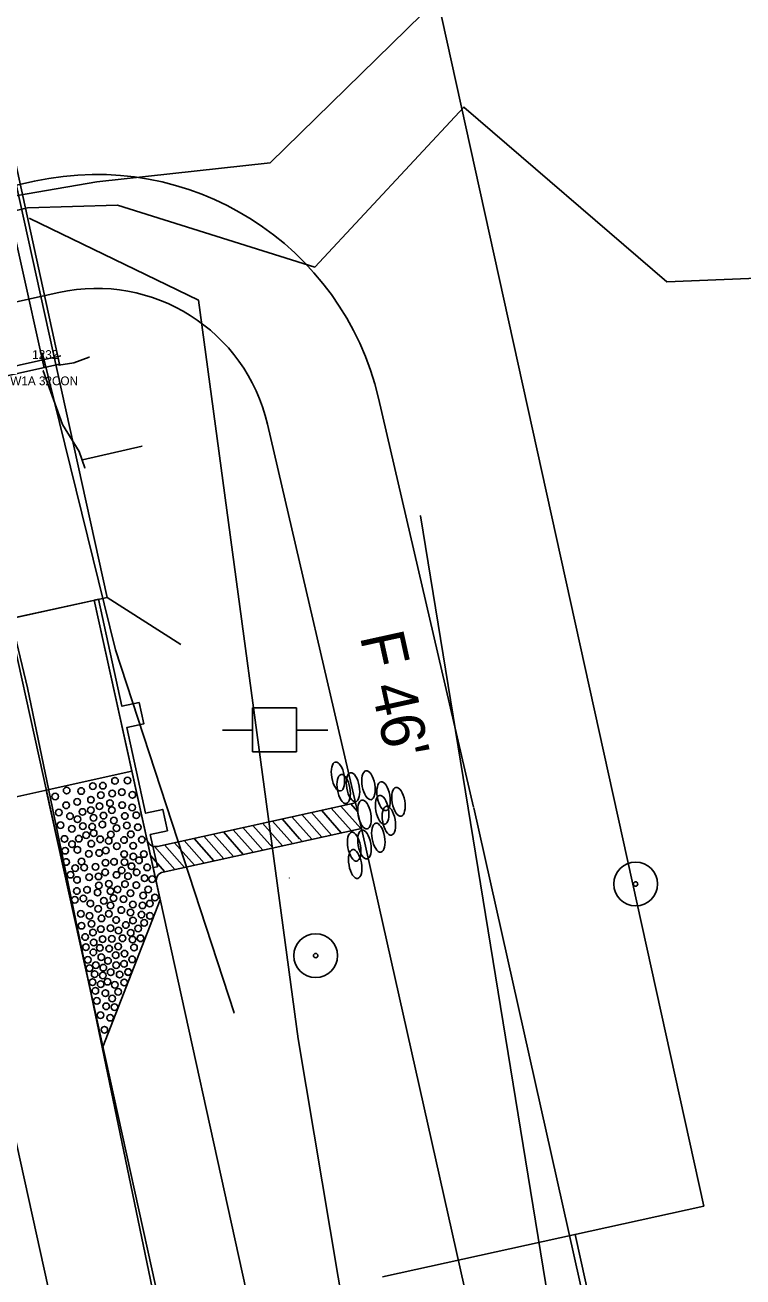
# Model space of a CAD drawing. Extents: x 2519952 to 2531965, y 848341 to 887632.
# Drawn here: x 2525647.4 to 2525729.3, y 850776.4 to 850919.3 of the extents above; entities that cross this region are included whole.
import ezdxf

# ---------------------------------------------------------------- set-up
doc = ezdxf.new("R2010")
doc.units = 0
for name, color, linetype in [('RD_EV_JW', 7, 'Continuous'), ('RD_EX_BldgApp', 7, 'Continuous'), ('RD_EX_BldgApp_txCode', 7, 'Continuous'), ('RD_EX_Bridge', 7, 'Continuous'), ('RD_EX_Conc', 7, 'Continuous'), ('RD_EX_DR_Pipe', 7, 'Continuous'), ('RD_EX_DV_Prop', 7, 'Continuous'), ('RD_EX_DV_PropPin', 7, 'Continuous'), ('RD_EX_GuardRail', 7, 'Continuous'), ('RD_EX_H2O', 7, 'Continuous'), ('RD_EX_Misc', 7, 'Continuous'), ('RD_EX_Road', 7, 'Continuous'), ('RD_EX_RW', 7, 'Continuous'), ('RD_EX_UT', 7, 'Continuous'), ('RD_EX_VEG', 7, 'Continuous'), ('RD_HC_Cl', 7, 'Continuous'), ('RD_PD_Bridge', 7, 'Continuous'), ('RD_PD_CstnLmt', 7, 'Continuous'), ('RD_PD_DR_ErosCtrl', 7, 'Continuous'), ('RD_PD_Final_TrvlWay', 7, 'Continuous'), ('RD_PD_GR', 7, 'Continuous'), ('RD_PD_PaveShd', 7, 'Continuous'), ('RD_PD_RW', 7, 'Continuous'), ('RD_PD_TX_CstnLmt', 7, 'Continuous'), ('RD_SMD_Locator', 7, 'Continuous')]:
    doc.layers.add(name, color=color, linetype=linetype)

# ---------------------------------------------------------------- blocks, each defined once
blk = doc.blocks.new('TBC1')
at = {"layer": 'RD_PD_GR'}
blk.add_lwpolyline([(12.5, 2.5), (15, 2.5), (15, 0.49), (25, 0.49), (25, 2.5), (27.5, 2.5), (27.5, 0.49), (31.25, 0.49), (31.25, 0), (0, 0), (0, 0.49), (12.5, 0.49)], close=True, dxfattribs=at)

msp = doc.modelspace()

# ---------------------------------------------------------------- linework, layer by layer
at = {"layer": 'RD_EV_JW'}
msp.add_lwpolyline([(2525775.02, 850342.8), (2525740.57, 850502.29), (2525718.16, 850607.75), (2525694.09, 850711.08), (2525678.58, 850803.56), (2525667.22, 850887.85), (2525647.98, 850897.19)], dxfattribs=at)
at = {"layer": 'RD_EX_BldgApp'}
msp.add_lwpolyline([(2525649.6, 850880.16), (2525641.48, 850916.68), (2525633.46, 850954.22)], dxfattribs=at)
at = {"layer": 'RD_EX_Bridge'}
for points in [[(2525605.06, 850870.31), (2525651.35, 850880.55), (2525635.22, 850954.61), (2525588.3, 850944.15), (2525605.06, 850870.31)], [(2525651.3, 850880.44), (2525653, 850880.72), (2525654.76, 850881.37)]]:
    msp.add_lwpolyline(points, dxfattribs=at)
at = {"layer": 'RD_EX_Conc'}
msp.add_lwpolyline([(2525654.27, 850868.73), (2525653.61, 850870.6), (2525651.69, 850873.67), (2525649.52, 850879.82)], dxfattribs=at)
at = {"layer": 'RD_EX_DR_Pipe'}
msp.add_line((2525654, 850869.64), (2525660.78, 850871.21), dxfattribs=at)
at = {"layer": 'RD_EX_DV_Prop'}
for p, q in [((2525660.31, 851077.44), (2525724.82, 850784.46)), ((2525724.82, 850784.46), (2525688.2, 850776.39))]:
    msp.add_line(p, q, dxfattribs=at)
at = {"layer": 'RD_EX_DV_PropPin'}
for centre, radius in [((2525717.05, 850821.24), 2.5), ((2525717.05, 850821.24), 0.25), ((2525680.57, 850813.07), 2.5), ((2525680.57, 850813.07), 0.25)]:
    msp.add_circle(centre, radius, dxfattribs=at)
at = {"layer": 'RD_EX_GuardRail'}
msp.add_lwpolyline([(2525671.27, 850806.53), (2525657.76, 850847.98), (2525649.43, 850881.8)], dxfattribs=at)
at = {"layer": 'RD_EX_H2O'}
for points in [[(2525412.97, 850559.06), (2525428.27, 850649.7), (2525457.74, 850694.47), (2525453.92, 850721), (2525416.74, 850748.14), (2525431.1, 850766.83), (2525463.21, 850790.4), (2525509.32, 850829.77), (2525574.87, 850869.61), (2525599.53, 850891.71), (2525655.63, 850901.38), (2525655.63, 850901.38), (2525675.39, 850903.55), (2525720.41, 850947.65)], [(2525657.98, 850898.71), (2525680.46, 850891.64), (2525697.48, 850909.91), (2525720.59, 850889.96), (2525757.95, 850891.5), (2525796.51, 850902.22), (2525808.33, 850876.08)], [(2525622.89, 850733.84), (2525593.83, 850844.27), (2525586.42, 850855.44), (2525600.63, 850887.26), (2525647.72, 850898.42), (2525657.98, 850898.71)]]:
    msp.add_lwpolyline(points, dxfattribs=at)
at = {"layer": 'RD_EX_Misc'}
msp.add_line((2525604.58, 850871.02), (2525651.5, 850881.5), dxfattribs=at)
at = {"layer": 'RD_EX_Road'}
for p, q in [((2525647.73, 850843.63), (2525639.53, 850877.6)), ((2525668.13, 850745.17), (2525647.73, 850843.63))]:
    msp.add_line(p, q, dxfattribs=at)
at = {"layer": 'RD_EX_RW'}
for p in [(2525660.31, 851077.44), (2525688.2, 850776.39)]:
    msp.add_line(p, (2525724.82, 850784.46), dxfattribs=at)
at = {"layer": 'RD_EX_UT'}
for p, q in [((2525678.38, 850841.34), (2525673.38, 850841.34)), ((2525673.38, 850841.34), (2525673.38, 850836.34)), ((2525678.38, 850836.34), (2525678.38, 850841.34)), ((2525669.95, 850838.78), (2525673.42, 850838.78)), ((2525678.31, 850838.78), (2525681.95, 850838.78)), ((2525673.38, 850836.34), (2525678.38, 850836.34))]:
    msp.add_line(p, q, dxfattribs=at)
at = {"layer": 'RD_EX_VEG'}
msp.add_lwpolyline([(2525828.9, 850368.68), (2525796.32, 850351.78), (2525755.08, 850564.16), (2525710.49, 850752.88), (2525692.51, 850863.27)], dxfattribs=at)
at = {"layer": 'RD_HC_Cl'}
msp.add_line((2525471.32, 851586.92), (2526027.91, 849059.27), dxfattribs=at)
at = {"layer": 'RD_PD_Bridge'}
for p, q in [((2525610.88, 850843.85), (2525656.79, 850853.95)), ((2525655.32, 850853.63), (2525659.62, 850834.1)), ((2525656.79, 850853.95), (2525665.21, 850848.57)), ((2525659.62, 850834.1), (2525616.65, 850824.64))]:
    msp.add_line(p, q, dxfattribs=at)
for points in [[(2525656.79, 850853.95), (2525628.83, 850980.91)], [(2525610.88, 850843.85), (2525656.79, 850853.95)]]:
    msp.add_lwpolyline(points, dxfattribs=at)
at = {"layer": 'RD_PD_CstnLmt'}
for p, q in [((2525675.07, 850873.73), (2525685.91, 850827.08)), ((2525685.91, 850827.08), (2525707.76, 850729.5))]:
    msp.add_line(p, q, dxfattribs=at)
msp.add_lwpolyline([(2525600.75, 850877.61), (2525651.29, 850888.74)], dxfattribs=at)
msp.add_arc((2525655.59, 850869.21), 20, 13.0724, 102.4185, dxfattribs=at)
at = {"layer": 'RD_PD_DR_ErosCtrl'}
for p, q in [((2525687.74, 850876.67), (2525698.57, 850830.02)), ((2525698.59, 850829.93), (2525720.45, 850732.34))]:
    msp.add_line(p, q, dxfattribs=at)
msp.add_lwpolyline([(2525597.95, 850890.31), (2525648.5, 850901.44)], dxfattribs=at)
msp.add_arc((2525655.59, 850869.21), 33, 13.0724, 102.4185, dxfattribs=at)
at = {"layer": 'RD_PD_Final_TrvlWay'}
msp.add_line((2525571.9, 851185.96), (2525846.09, 849940.79), dxfattribs=at)
at = {"layer": 'RD_PD_GR'}
msp.add_line((2525662.04, 850823.11), (2525820.64, 850102.87), dxfattribs=at)
at = {"layer": 'RD_PD_PaveShd'}
for p, q in [((2525649.86, 850831.95), (2525659.62, 850834.1)), ((2525659.62, 850834.1), (2525661.56, 850825.31)), ((2525649.86, 850831.95), (2525656.31, 850802.65)), ((2525685.11, 850830.51), (2525662.53, 850825.52)), ((2525683.45, 850830.14), (2525685.73, 850827.57)), ((2525683.45, 850830.14), (2525685.73, 850827.57)), ((2525684.57, 850830.39), (2525685.34, 850829.52)), ((2525685.79, 850827.59), (2525685.11, 850830.51)), ((2525676.75, 850828.66), (2525678.74, 850826.41)), ((2525676.75, 850828.66), (2525679.03, 850826.09)), ((2525677.87, 850828.91), (2525680.14, 850826.34)), ((2525677.87, 850828.91), (2525680.14, 850826.34)), ((2525678.99, 850829.16), (2525681.26, 850826.59)), ((2525678.99, 850829.16), (2525681.26, 850826.59)), ((2525680.1, 850829.4), (2525682.38, 850826.83)), ((2525680.1, 850829.4), (2525682.38, 850826.83)), ((2525681.22, 850829.65), (2525683.49, 850827.08)), ((2525681.22, 850829.65), (2525683.49, 850827.08)), ((2525682.34, 850829.9), (2525684.61, 850827.33)), ((2525682.34, 850829.9), (2525684.61, 850827.33)), ((2525663.18, 850822.59), (2525685.79, 850827.59)), ((2525670.05, 850827.18), (2525672.32, 850824.61)), ((2525670.05, 850827.18), (2525672.32, 850824.61)), ((2525671.17, 850827.43), (2525673.44, 850824.86)), ((2525671.17, 850827.43), (2525673.44, 850824.86)), ((2525672.28, 850827.68), (2525674.56, 850825.11)), ((2525672.28, 850827.68), (2525674.56, 850825.11)), ((2525673.4, 850827.92), (2525675.67, 850825.35)), ((2525673.4, 850827.92), (2525675.67, 850825.35)), ((2525674.52, 850828.17), (2525676.79, 850825.6)), ((2525674.52, 850828.17), (2525676.79, 850825.6)), ((2525675.63, 850828.42), (2525677.91, 850825.85)), ((2525675.63, 850828.42), (2525677.91, 850825.85)), ((2525663.35, 850825.7), (2525665.62, 850823.13)), ((2525663.35, 850825.7), (2525665.62, 850823.13)), ((2525664.46, 850825.95), (2525666.74, 850823.38)), ((2525664.46, 850825.95), (2525666.74, 850823.38)), ((2525665.58, 850826.2), (2525667.85, 850823.63)), ((2525665.58, 850826.2), (2525667.85, 850823.63)), ((2525666.7, 850826.44), (2525668.97, 850823.87)), ((2525667.82, 850826.69), (2525670.09, 850824.12)), ((2525667.82, 850826.69), (2525670.09, 850824.12)), ((2525668.93, 850826.94), (2525671.21, 850824.37)), ((2525668.93, 850826.94), (2525671.21, 850824.37)), ((2525661.56, 850825.31), (2525662.2, 850822.38)), ((2525661.73, 850824.51), (2525663.39, 850822.64)), ((2525662.18, 850825.51), (2525664.5, 850822.89)), ((2525662.2, 850822.38), (2525662.85, 850819.45)), ((2525656.31, 850802.65), (2525662.85, 850819.45))]:
    msp.add_line(p, q, dxfattribs=at)
for centre in [(2525655.16, 850832.41), (2525655.16, 850832.41), (2525656.31, 850832.46), (2525656.31, 850832.46), (2525657.69, 850833.02), (2525657.69, 850833.02), (2525659.12, 850833.04), (2525659.12, 850833.04), (2525659.12, 850833.04), (2525650.87, 850831.22), (2525650.87, 850831.22), (2525652.18, 850831.9), (2525652.18, 850831.9), (2525653.83, 850831.85), (2525653.83, 850831.85), (2525656.07, 850831.38), (2525656.07, 850831.38), (2525657.38, 850831.58), (2525657.38, 850831.58), (2525658.48, 850831.73), (2525658.48, 850831.73), (2525659.67, 850831.41), (2525659.67, 850831.41), (2525652.13, 850830.22), (2525652.13, 850830.22), (2525653.39, 850830.61), (2525653.39, 850830.61), (2525654.94, 850829.66), (2525654.94, 850829.66), (2525654.95, 850830.86), (2525654.95, 850830.86), (2525655.91, 850830.12), (2525655.91, 850830.12), (2525657.12, 850830.46), (2525657.12, 850830.46), (2525657.32, 850829.67), (2525657.32, 850829.67), (2525658.5, 850830.25), (2525658.5, 850830.25), (2525659.64, 850829.98), (2525659.64, 850829.98), (2525651.29, 850829.4), (2525651.29, 850829.4), (2525652.56, 850828.98), (2525652.56, 850828.98), (2525653.41, 850828.63), (2525653.41, 850828.63), (2525653.99, 850829.46), (2525653.99, 850829.46), (2525655.24, 850828.79), (2525655.24, 850828.79), (2525656.39, 850829.04), (2525656.39, 850829.04), (2525657.56, 850828.49), (2525657.56, 850828.49), (2525658.8, 850829), (2525658.8, 850829), (2525660.12, 850829.08), (2525660.12, 850829.08), (2525651.49, 850827.95), (2525651.49, 850827.95), (2525652.78, 850827.54), (2525652.78, 850827.54), (2525654.03, 850827.85), (2525654.03, 850827.85), (2525654.4, 850826.81), (2525654.4, 850826.81), (2525655.09, 850827.78), (2525655.26, 850827.03), (2525655.26, 850827.03), (2525656.25, 850828.04), (2525656.25, 850828.04), (2525657.21, 850826.88), (2525657.21, 850826.88), (2525657.87, 850827.6), (2525657.87, 850827.6), (2525659.05, 850827.92), (2525659.05, 850827.92), (2525659.49, 850826.91), (2525659.49, 850826.91), (2525660.3, 850827.71), (2525660.3, 850827.71), (2525651.92, 850826.38), (2525651.92, 850826.38), (2525652.79, 850825.78), (2525652.79, 850825.78), (2525653.56, 850826.41), (2525653.56, 850826.41), (2525654.99, 850825.84), (2525654.99, 850825.84), (2525655.99, 850826.34), (2525655.99, 850826.34), (2525656.97, 850826.17), (2525656.97, 850826.17), (2525657.89, 850825.55), (2525657.89, 850825.55), (2525658.72, 850826.26), (2525658.72, 850826.26), (2525659.77, 850825.61), (2525659.77, 850825.61), (2525660.74, 850826.3), (2525660.74, 850826.3), (2525652.02, 850825.04), (2525652.02, 850825.04), (2525653.4, 850825.13), (2525653.4, 850825.13), (2525654.72, 850824.68), (2525654.72, 850824.68), (2525655.88, 850824.78), (2525655.88, 850824.78), (2525656.65, 850825.07), (2525656.65, 850825.07), (2525658.73, 850824.66), (2525658.73, 850824.66), (2525659.78, 850824.37), (2525659.78, 850824.37), (2525660.43, 850823.94), (2525660.43, 850823.94), (2525660.98, 850824.66), (2525660.98, 850824.66), (2525652.11, 850823.75), (2525652.11, 850823.75), (2525653.16, 850823.06), (2525653.16, 850823.06), (2525653.88, 850823.81), (2525653.88, 850823.81), (2525654.18, 850823.11), (2525654.18, 850823.11), (2525655.47, 850823.2), (2525655.47, 850823.2), (2525656.58, 850822.57), (2525656.58, 850822.57), (2525656.62, 850823.67), (2525656.62, 850823.67), (2525657.58, 850823.78), (2525657.58, 850823.78), (2525658.45, 850822.8), (2525658.45, 850822.8), (2525658.78, 850823.73), (2525658.78, 850823.73), (2525659.57, 850823.26), (2525659.57, 850823.26), (2525660.16, 850822.57), (2525660.16, 850822.57), (2525661.37, 850823.14), (2525661.37, 850823.14), (2525652.62, 850822.3), (2525653.36, 850821.7), (2525653.36, 850821.7), (2525654.75, 850822.01), (2525654.75, 850822.01), (2525655.8, 850822.11), (2525655.8, 850822.11), (2525655.85, 850821.08), (2525655.85, 850821.08), (2525656.98, 850821.26), (2525656.98, 850821.26), (2525657.86, 850822.27), (2525657.86, 850822.27), (2525658.83, 850821.23), (2525658.83, 850821.23), (2525659.17, 850822.13), (2525659.17, 850822.13), (2525660.12, 850821.12), (2525660.12, 850821.12), (2525661.07, 850821.9), (2525661.07, 850821.9), (2525661.92, 850821.78), (2525661.92, 850821.78), (2525653.34, 850820.44), (2525653.34, 850820.44), (2525654.08, 850819.58), (2525654.08, 850819.58), (2525654.5, 850820.57), (2525654.5, 850820.57), (2525655.71, 850820.27), (2525655.71, 850820.27), (2525657.18, 850820.43), (2525657.18, 850820.43), (2525657.53, 850819.63), (2525657.53, 850819.63), (2525657.99, 850820.6), (2525657.99, 850820.6), (2525659.47, 850820.18), (2525659.47, 850820.18), (2525660.89, 850819.92), (2525660.89, 850819.92), (2525661.47, 850820.61), (2525661.47, 850820.61), (2525662.25, 850819.69), (2525662.25, 850819.69), (2525662.25, 850819.69), (2525653.12, 850819.44), (2525653.12, 850819.44), (2525654.88, 850819), (2525654.88, 850819), (2525655.78, 850818.41), (2525655.78, 850818.41), (2525656.41, 850819.33), (2525656.41, 850819.33), (2525657.17, 850818.78), (2525657.17, 850818.78), (2525658.41, 850818.27), (2525658.41, 850818.27), (2525658.65, 850819.52), (2525658.65, 850819.52), (2525659.73, 850818.89), (2525659.73, 850818.89), (2525660.82, 850818.8), (2525660.82, 850818.8), (2525661.65, 850819), (2525661.65, 850819), (2525653.8, 850817.83), (2525653.8, 850817.83), (2525654.79, 850817.6), (2525654.79, 850817.6), (2525655, 850816.69), (2525655, 850816.69), (2525656.16, 850817.32), (2525656.16, 850817.32), (2525657, 850817.83), (2525657, 850817.83), (2525657.83, 850817.13), (2525657.83, 850817.13), (2525659.45, 850817.99), (2525659.45, 850817.99), (2525659.74, 850817.07), (2525659.74, 850817.07), (2525660.7, 850817.74), (2525660.7, 850817.74), (2525661.01, 850816.8), (2525661.01, 850816.8), (2525661.68, 850817.6), (2525661.68, 850817.6), (2525653.86, 850816.48), (2525653.86, 850816.48), (2525655.18, 850815.7), (2525655.18, 850815.7), (2525656.08, 850816.1), (2525656.08, 850816.1), (2525657.18, 850816.19), (2525657.18, 850816.19), (2525658.09, 850815.94), (2525658.09, 850815.94), (2525658.92, 850816.56), (2525658.92, 850816.56), (2525659.48, 850815.66), (2525659.48, 850815.66), (2525660.33, 850816.16), (2525660.33, 850816.16), (2525654.29, 850815.19), (2525654.29, 850815.19), (2525654.38, 850814.04), (2525654.38, 850814.04), (2525655.26, 850814.57), (2525655.26, 850814.57), (2525655.96, 850813.94), (2525655.96, 850813.94), (2525656.28, 850814.94), (2525656.28, 850814.94), (2525657.02, 850813.86), (2525657.02, 850813.86), (2525657.34, 850814.98), (2525657.34, 850814.98), (2525658.05, 850814.12), (2525658.05, 850814.12), (2525658.54, 850815.04), (2525658.54, 850815.04), (2525659.69, 850814.89), (2525659.69, 850814.89), (2525659.86, 850813.98), (2525659.86, 850813.98), (2525660.6, 850815.04), (2525660.6, 850815.05), (2525654.6, 850812.58), (2525654.6, 850812.58), (2525655.22, 850813.44), (2525655.22, 850813.44), (2525656.13, 850812.89), (2525656.13, 850812.89), (2525656.89, 850812.46), (2525656.89, 850812.46), (2525657.77, 850813.11), (2525657.77, 850813.11), (2525658.77, 850813.29), (2525658.77, 850813.29), (2525659.64, 850812.64), (2525659.64, 850812.64), (2525654.79, 850811.63), (2525654.79, 850811.63), (2525655.37, 850810.96), (2525655.37, 850810.96), (2525655.5, 850811.98), (2525655.5, 850811.98), (2525656.36, 850811.69), (2525656.36, 850811.69), (2525657.2, 850811.17), (2525657.2, 850811.17), (2525657.82, 850811.97), (2525657.82, 850811.97), (2525658.72, 850812.14), (2525658.72, 850812.14), (2525659.18, 850811.17), (2525659.19, 850811.2), (2525655.14, 850810.05), (2525655.14, 850810.05), (2525656.06, 850809.82), (2525656.06, 850809.82), (2525656.31, 850810.81), (2525656.31, 850810.81), (2525656.83, 850810.09), (2525656.83, 850810.09), (2525657.67, 850809.73), (2525657.67, 850809.73), (2525658.22, 850810.9), (2525658.22, 850810.9), (2525658.75, 850810.01), (2525658.75, 850810.01), (2525655.45, 850809.05), (2525655.45, 850809.05), (2525656.59, 850808.79), (2525656.59, 850808.79), (2525657.38, 850808.16), (2525657.38, 850808.16), (2525658.04, 850808.94), (2525655.63, 850807.9), (2525655.63, 850807.9), (2525656.69, 850807.28), (2525656.69, 850807.28), (2525657.63, 850807.19), (2525657.63, 850807.19), (2525656.05, 850806.26), (2525656.05, 850806.26), (2525657.15, 850805.98), (2525657.15, 850805.98), (2525656.48, 850804.61)]:
    msp.add_circle(centre, 0.375, dxfattribs=at)
for centre, start, end in [((2525662.32, 850826.5), 192.4185, 282.4481), ((2525663.39, 850821.62), 102.4481, 192.4185)]:
    msp.add_arc(centre, 1, start, end, dxfattribs=at)
for centre in [(2525683.11, 850833.51), (2525683.11, 850833.51), (2525686.59, 850832.51), (2525686.59, 850832.51), (2525683.76, 850832.08), (2525683.76, 850832.08), (2525684.83, 850832.29), (2525684.83, 850832.29), (2525688.31, 850831.26), (2525688.31, 850831.26), (2525688.15, 850829.7), (2525688.15, 850829.7), (2525690.01, 850830.62), (2525690.01, 850830.62), (2525686.14, 850829.17), (2525686.14, 850829.17), (2525688.92, 850828.47), (2525688.92, 850828.47), (2525684.96, 850825.5), (2525686.14, 850825.75), (2525686.14, 850825.75), (2525687.71, 850826.53), (2525687.71, 850826.53), (2525685.08, 850823.52)]:
    msp.add_ellipse(centre, major_axis=(0.29, -1.65), ratio=0.429445, dxfattribs=at)
at = {"layer": 'RD_PD_RW'}
msp.add_line((2525710.17, 850781.23), (2525817.7, 850292.93), dxfattribs=at)
at = {"layer": 'RD_SMD_Locator'}
for centre in [(2525697.48, 850909.91), (2525675.39, 850903.55), (2525655.63, 850901.38), (2525655.63, 850901.38), (2525657.98, 850898.71), (2525657.98, 850898.71), (2525647.72, 850898.42), (2525647.98, 850897.19), (2525680.46, 850891.64), (2525720.59, 850889.96), (2525667.22, 850887.85), (2525649.43, 850881.8), (2525651.5, 850881.5), (2525654.76, 850881.37), (2525649.6, 850880.16), (2525651.3, 850880.44), (2525651.35, 850880.55), (2525653, 850880.72), (2525649.52, 850879.82), (2525651.69, 850873.67), (2525653.61, 850870.6), (2525660.78, 850871.21), (2525654, 850869.64), (2525654.27, 850868.73), (2525692.51, 850863.27), (2525657.76, 850847.98), (2525647.73, 850843.63), (2525677.55, 850821.94), (2525671.27, 850806.53), (2525678.58, 850803.56)]:
    msp.add_circle(centre, 0.001, dxfattribs=at)

# ---------------------------------------------------------------- block references
at = {"layer": 'RD_PD_Bridge', "rotation": -77.58151740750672}
msp.add_blockref('TBC1', (2525655.32, 850853.63), dxfattribs=at)

# ---------------------------------------------------------------- texts
at = {"layer": 'RD_EX_BldgApp_txCode'}
for s, p in [('1232', (2525648.25, 850881.16)), ('W1A 32CON', (2525645.75, 850878.16))]:
    msp.add_text(s, height=1, dxfattribs=at).set_placement(p)
at = {"layer": 'RD_PD_TX_CstnLmt'}
msp.add_text("F 46'", height=5, rotation=282.4185, dxfattribs=at).set_placement((2525685.59, 850849.52))

doc.saveas('drawing.dxf')
